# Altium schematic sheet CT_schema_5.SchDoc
size 287 x 160 mm
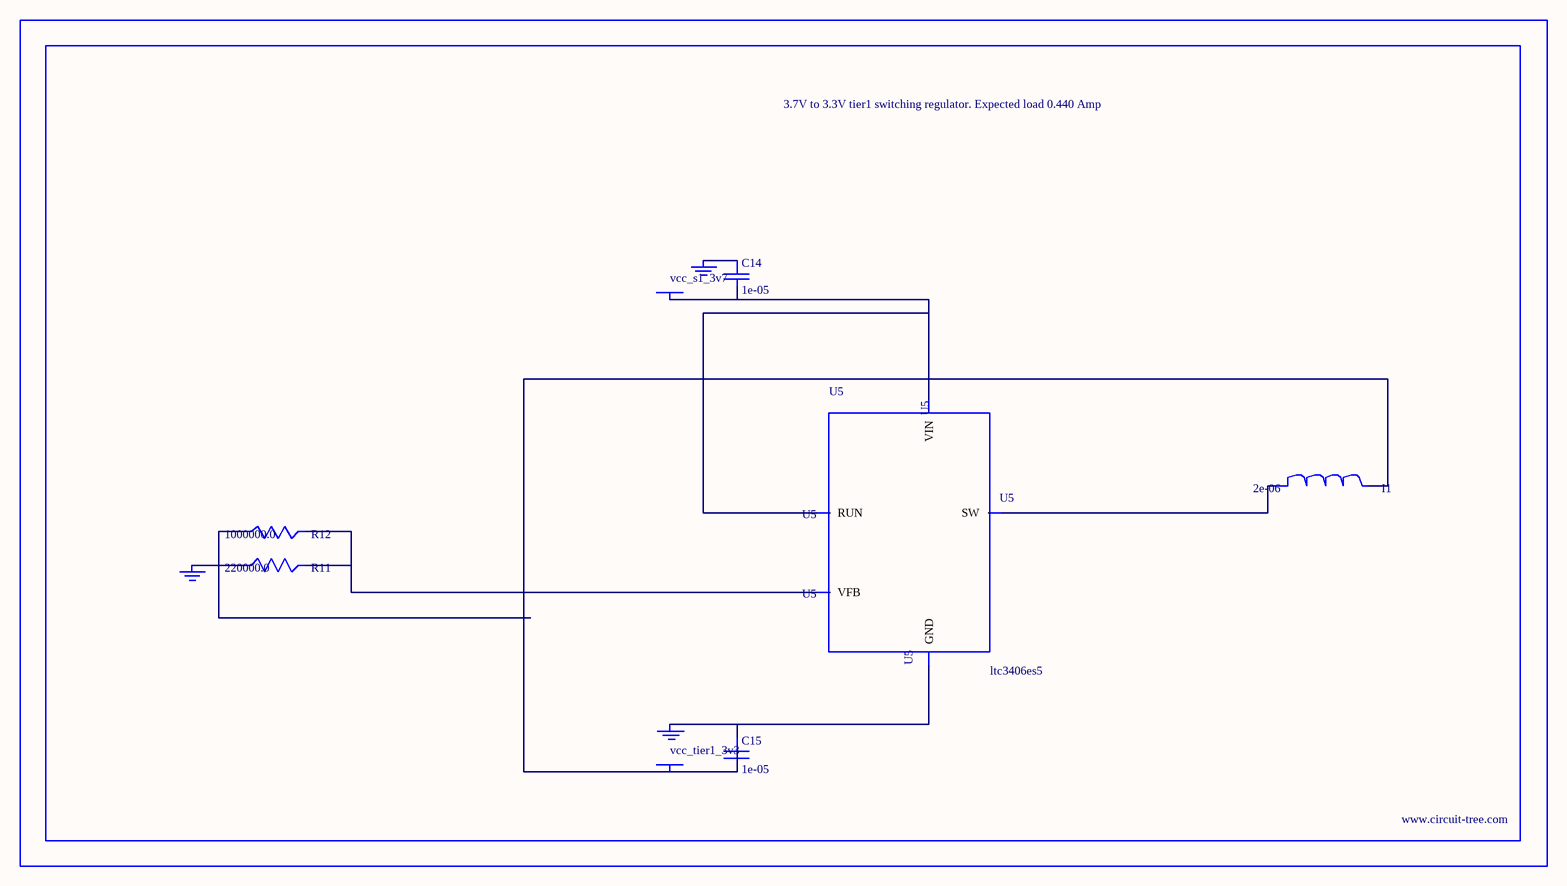
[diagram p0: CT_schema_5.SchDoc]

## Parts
BORDER4  (no value)
C14  1e-05  [C0805]
C15  1e-05  [C0805]
GND_INSTANCE_4_0  (no value)
GND_INSTANCE_4_1  (no value)
GND_INSTANCE_4_2  (no value)
I1  2e-06  [WE-HCI_7030/7040/7050]
POWER_INSTANCE_4_0  vcc_tier1_3v3
POWER_INSTANCE_4_1  vcc_s1_3v7
R11  220000.0  [R0603]
R12  1000000.0  [R0603]
U5  ltc3406es5  [TSOT-23-5]

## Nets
NetC14_1: C14.1 GND_INSTANCE_4_1.0(GND)
NetC14_2: C14.2 POWER_INSTANCE_4_1.0(PWR) U5.1(RUN) U5.4(VIN)
NetC15_1: C15.1 GND_INSTANCE_4_0.0(GND) U5.2(GND)
NetC15_2: C15.2 I1.2 POWER_INSTANCE_4_0.0(PWR) R12.1
NetGND_INSTANCE_4_2_0: GND_INSTANCE_4_2.0(GND) R11.1
NetI1_1: I1.1 U5.3(SW)
NetR11_2: R11.2 R12.2 U5.5(VFB)

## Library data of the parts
BORDER4 = BORDER_PAGE4
C14 C15 = C0805C106K8RACTU
GND_INSTANCE_4_0-GND_INSTANCE_4_2 = GND
I1 = 744314200
POWER_INSTANCE_4_0 POWER_INSTANCE_4_1 = PWR
R11 = RC0603JR-07220KL
R12 = RC0603JR-071ML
